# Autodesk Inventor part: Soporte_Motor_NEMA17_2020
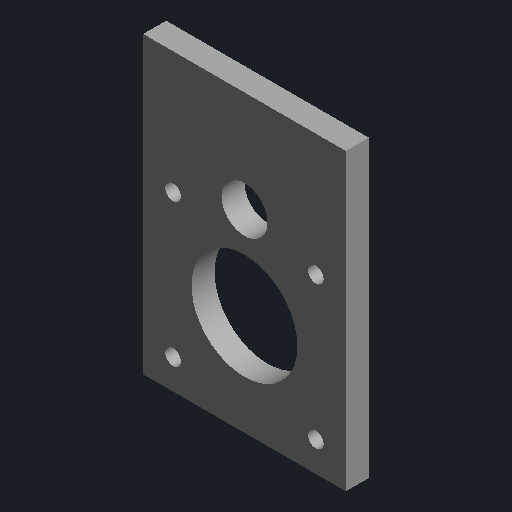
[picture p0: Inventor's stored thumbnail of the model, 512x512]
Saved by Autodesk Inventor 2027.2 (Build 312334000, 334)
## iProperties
Part Number: Soporte_Motor_NEMA17_2020
Material: Genérico
Document SubType Name: Modelado
Designer: Usuario
Appearance: Por defecto
Author: Usuario
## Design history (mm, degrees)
sketch "Boceto1"
  geometry: L1 (-22, -22)-(22, -22); L2 (22, -22)-(22, 42); L3 (22, 42)-(-22, 42); L4 (-22, 42)-(-22, -22); C1 r 11.5 at (0, 0); C2 r 1.7 at (-15.5, -15.5); C3 r 1.7 at (15.5, -15.5); C4 r 1.7 at (-15.5, 15.5); C5 r 1.7 at (15.5, 15.5); C6 r 5 at (0, 20)
  constraints: 8 end point, 6 centre point, 2 parallel, 1 horizontal, 1 perpendicular
extrude "Extrusión1" new body sketch "Boceto1" distance "d0" = 5; taper "d1" = 0 deg
node "Sólido1"
node "Cuerpos sólidos"
node "Cuerpos de superficie"
